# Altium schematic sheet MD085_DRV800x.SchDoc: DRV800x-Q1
size 431 x 279 mm; VersionControl_RevNumber: 1; Date: Not shown in title block; ApprovedBy: Not shown in title block; CheckedBy: Not shown in title block; Author: Not shown in title block; CompanyName: Not shown in title block; DrawnBy: Keerthi Kumanan; Engineer: Not shown in title block; Organization: Not shown in title block; Address1: Not shown in title block; Address2: Not shown in title block; Address3: Not shown in title block; Address4: Not shown in title block; DocumentNumber: 1; Revision: 1; SheetNumber: 4; SheetTotal: 1; PageSetup: Record=PageOptions¦CenterHorizontal=True¦CenterVertical=True¦PrintScale=1.00¦XCorrection=1.00¦YCorrection=1.00¦PrintKind=0¦BorderSize=5000000¦LeftOffset=0¦BottomOffset=0¦Orientation=2¦PaperLength=1000¦PaperWidth=1000¦Scale=100¦PaperSource=15¦PrintQuality=600¦MediaType=1¦DitherType=10¦PaperKind=Letter¦PrintScaleMode=1; VersionControl_ProjFolderRevNumber: 1; VersionControl_RevNumberShort: 1; VersionControl_ProjFolderRevNumberShort: 1
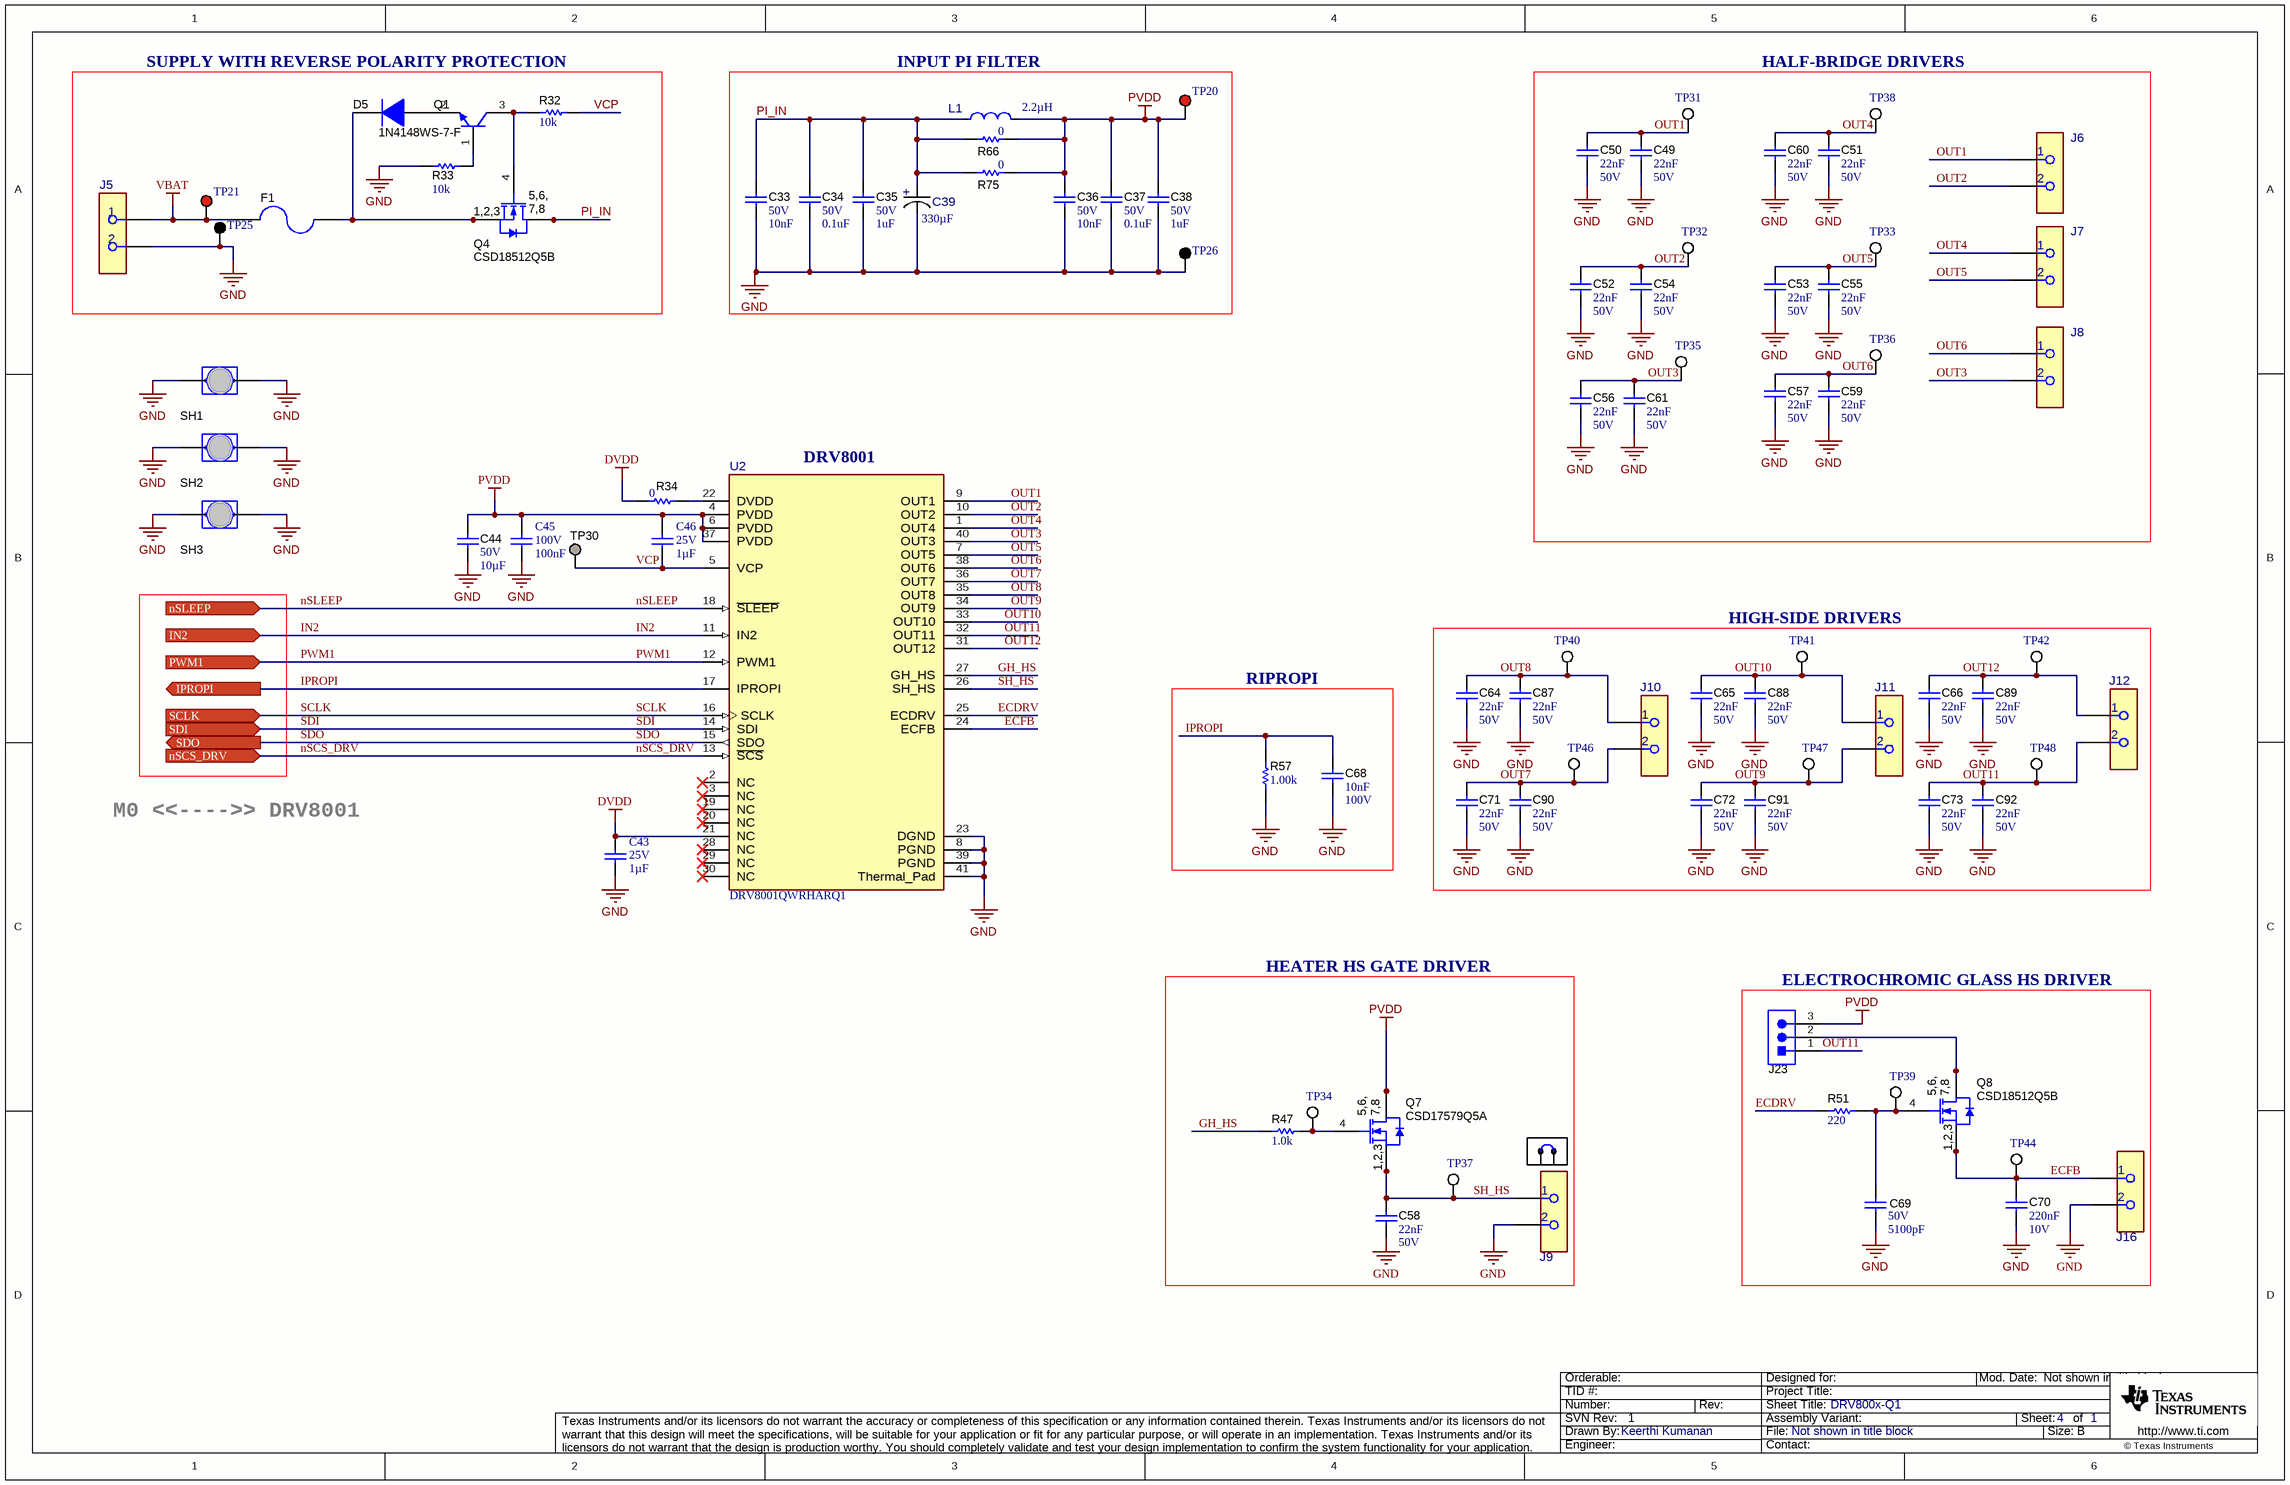
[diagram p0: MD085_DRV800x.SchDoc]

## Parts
C33  VDC_V: 50V  Cap_F: 10nF  [0603L]  (hidden comment: 885012206089)
C34  VDC_V: 50V  ValueDisplayed: 0.1uF  [0603]  (hidden comment: 885012206095)
C35  VDC_V: 50V  ValueDisplayed: 1uF  [0805L]  (hidden comment: 885012207103)
C36  VDC_V: 50V  Cap_F: 10nF  [0603L]  (hidden comment: 885012206089)
C37  VDC_V: 50V  ValueDisplayed: 0.1uF  [0603]  (hidden comment: 885012206095)
C38  VDC_V: 50V  ValueDisplayed: 1uF  [0805L]  (hidden comment: 885012207103)
C39  Cap_F: 330µF  [FP-860020675021_RADIAL-MFG]  (hidden comment: 860020675021)
C43  value 1µF  Rated Voltage (DC): 25V  [WCAP-CSGP_0603_L1.6W0.8H0.8_Reflow]  (hidden comment: 885012206076)
C44  VDC_V: 50V  ValueDisplayed: 10µF  [1206_180]  (hidden comment: 885012108022)
C45  value 100nF  Rated Voltage (DC): 100V  [WCAP-CSGP_0603_L1.6W0.8H0.8_Reflow]  (hidden comment: 885012206120)
C46  value 1µF  Rated Voltage (DC): 25V  [WCAP-CSGP_0603_L1.6W0.8H0.8_Reflow]  (hidden comment: 885012206076)
C49  Cap_F: 22nF  VDC_V: 50V  [0603]  (hidden comment: 885012206091)
C50  Cap_F: 22nF  VDC_V: 50V  [0603]  (hidden comment: 885012206091)
C51  Cap_F: 22nF  VDC_V: 50V  [0603]  (hidden comment: 885012206091)
C52  Cap_F: 22nF  VDC_V: 50V  [0603]  (hidden comment: 885012206091)
C53  Cap_F: 22nF  VDC_V: 50V  [0603]  (hidden comment: 885012206091)
C54  Cap_F: 22nF  VDC_V: 50V  [0603]  (hidden comment: 885012206091)
C55  Cap_F: 22nF  VDC_V: 50V  [0603]  (hidden comment: 885012206091)
C56  Cap_F: 22nF  VDC_V: 50V  [0603]  (hidden comment: 885012206091)
C57  Cap_F: 22nF  VDC_V: 50V  [0603]  (hidden comment: 885012206091)
C58  Cap_F: 22nF  VDC_V: 50V  [0603]  (hidden comment: 885012206091)
C59  Cap_F: 22nF  VDC_V: 50V  [0603]  (hidden comment: 885012206091)
C60  Cap_F: 22nF  VDC_V: 50V  [0603]  (hidden comment: 885012206091)
C61  Cap_F: 22nF  VDC_V: 50V  [0603]  (hidden comment: 885012206091)
C64  Cap_F: 22nF  VDC_V: 50V  [0603]  (hidden comment: 885012206091)
C65  Cap_F: 22nF  VDC_V: 50V  [0603]  (hidden comment: 885012206091)
C66  Cap_F: 22nF  VDC_V: 50V  [0603]  (hidden comment: 885012206091)
C68  Cap_F: 10nF  VDC_V: 100V  [0603]  (hidden comment: 885012206114)
C69  VDC_V: 50V  ValueDisplayed: 5100pF  [0603]  (hidden comment: C0603C512J5GAC7867)
C70  Cap_F: 220nF  VDC_V: 10V  [0603]  (hidden comment: 885012206022)
C71  Cap_F: 22nF  VDC_V: 50V  [0603]  (hidden comment: 885012206091)
C72  Cap_F: 22nF  VDC_V: 50V  [0603]  (hidden comment: 885012206091)
C73  Cap_F: 22nF  VDC_V: 50V  [0603]  (hidden comment: 885012206091)
C87  Cap_F: 22nF  VDC_V: 50V  [0603]  (hidden comment: 885012206091)
C88  Cap_F: 22nF  VDC_V: 50V  [0603]  (hidden comment: 885012206091)
C89  Cap_F: 22nF  VDC_V: 50V  [0603]  (hidden comment: 885012206091)
C90  Cap_F: 22nF  VDC_V: 50V  [0603]  (hidden comment: 885012206091)
C91  Cap_F: 22nF  VDC_V: 50V  [0603]  (hidden comment: 885012206091)
C92  Cap_F: 22nF  VDC_V: 50V  [0603]  (hidden comment: 885012206091)
D5  1N4148WS-7-F  [SOD-323]
F1  0463030.ER  [Fuse_0463]  (value not drawn)
J5  691256610002  [FP-691256610002_HDR2-MFG]  (value not drawn)
J6  691250610002  [FP-691250610002_CONN_TERM_BLOCK2-MFG]  (value not drawn)
J7  691250610002  [FP-691250610002_CONN_TERM_BLOCK2-MFG]  (value not drawn)
J8  691250610002  [FP-691250610002_CONN_TERM_BLOCK2-MFG]  (value not drawn)
J9  691250610002  [FP-691250610002_CONN_TERM_BLOCK2-MFG]  (value not drawn)
J10  691216710002  [FP-691216710002_HDR2-MFG]  (value not drawn)
J11  691216710002  [FP-691216710002_HDR2-MFG]  (value not drawn)
J12  691216710002  [FP-691216710002_HDR2-MFG]  (value not drawn)
J16  691250610002  [FP-691250610002_CONN_TERM_BLOCK2-MFG]  (value not drawn)
J23  TSW-103-07-G-S  [TSW-103-07-G-S]  (value not drawn)
L1  Ind_H: 2.2µH  [FP-74439369022_IND_SMT_11MM6_10MM5-MFG]  (hidden comment: 74439369022)
Q1  BC846BLT1G  [SOT-23L]  (value not drawn)
Q4  CSD18512Q5B  [DNK0008A]
Q7  CSD17579Q5A  [DQJ0008A]
Q8  CSD18512Q5B  [DNK0008A]
R32  ValueDisplayed: 10k  [0603]  (hidden comment: RC0603JR-0710KL)
R33  ValueDisplayed: 10k  [0603]  (hidden comment: RC0603JR-0710KL)
R34  value 0  [0603]  (hidden comment: Resistor)
R47  ValueDisplayed: 1.0k  [0603]  (hidden comment: RC0603JR-071KL)
R51  ValueDisplayed: 220  [0603]  (hidden comment: RC0603FR-07220RL)
R57  ValueDisplayed: 1.00k  [0603]  (hidden comment: RC0603FR-071KL)
R66  ValueDisplayed: 0  [2512_084]  (hidden comment: HCJ2512ZT0R00)
R75  ValueDisplayed: 0  [2512_084]  (hidden comment: HCJ2512ZT0R00)
SH1  Jumper_2p  [Harwin_D3082-05]  (value not drawn)
SH2  Jumper_2p  [Harwin_D3082-05]  (value not drawn)
SH3  Jumper_2p  [Harwin_D3082-05]  (value not drawn)
SH-J21  60900213421  [Wurth_60900213421]  (value not drawn)
TP20  5010  [Keystone5010]  (value not drawn)
TP21  5010  [Keystone5010]  (value not drawn)
TP25  5011  [Keystone5011]  (value not drawn)
TP26  5011  [Keystone5011]  (value not drawn)
TP30  TP_H0.45P0.75  [TP_H045P075]  (value not drawn)  (no BOM)
TP31  5012  [Keystone5012]  (value not drawn)
TP32  5012  [Keystone5012]  (value not drawn)
TP33  5012  [Keystone5012]  (value not drawn)
TP34  5012  [Keystone5012]  (value not drawn)
TP35  5012  [Keystone5012]  (value not drawn)
TP36  5012  [Keystone5012]  (value not drawn)
TP37  5012  [Keystone5012]  (value not drawn)
TP38  5012  [Keystone5012]  (value not drawn)
TP39  5012  [Keystone5012]  (value not drawn)
TP40  5012  [Keystone5012]  (value not drawn)
TP41  5012  [Keystone5012]  (value not drawn)
TP42  5012  [Keystone5012]  (value not drawn)
TP44  5012  [Keystone5012]  (value not drawn)
TP46  5012  [Keystone5012]  (value not drawn)
TP47  5012  [Keystone5012]  (value not drawn)
TP48  5012  [Keystone5012]  (value not drawn)
U2  DRV8001QWRHARQ1  [RHA0040M-MFG]

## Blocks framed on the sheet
SUPPLY WITH REVERSE POLARITY PROTECTION: D5 F1 J5 Q1 Q4 R32 R33 TP21 TP25
INPUT PI FILTER: C33-C39 L1 R66 R75 TP20 TP26
HALF-BRIDGE DRIVERS: C49-C57 C59-C61 J6-J8 TP31-TP33 TP35 TP36 TP38
HIGH-SIDE DRIVERS: C64-C66 C71-C73 C87-C92 J10-J12 TP40-TP42 TP46-TP48
RIPROPI: C68 R57
HEATER HS GATE DRIVER: C58 J9 Q7 R47 SH-J21 TP34 TP37
ELECTROCHROMIC GLASS HS DRIVER: C69 C70 J16 J23 Q8 R51 TP39 TP44

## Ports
IN2 (in), IPROPI (out), nSCS_DRV (in), nSLEEP (in), PWM1 (in), SCLK (in), SDI (in), SDO (out)

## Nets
DVDD: C43.2 R34.2 U2.21(NC)
GND: C33.2 C34.2 C35.2 C36.2 C37.2 C38.2 C39.1(CATHODE) C43.1 C44.2 C45.1 C49.1 C50.1 C51.1 C52.1 C53.1 C54.1 C55.1 C56.1 C57.1 C58.1 C59.1 C60.1 C61.1 C64.1 C65.1 C66.1 C68.2 C69.2 C70.2 C71.1 C72.1 C73.1 C87.1 C88.1 C89.1 C90.1 C91.1 C92.1 J5.2 J9.2 J16.2 R33.1 R57.1 SH1.1 SH1.2 SH2.1 SH2.2 SH3.1 SH3.2 TP25.1 TP26.1 U2.8(PGND) U2.23(DGND) U2.39(PGND) U2.41(Thermal_Pad)
PVDD: C36.1 C37.1 C38.1 C44.1 C45.2 C46.2 J23.3 L1.2 Q7.5(D) Q7.6(D) Q7.7(D) Q7.8(D) Q7.9(D) R66.2 R75.2 TP20.1 U2.4(PVDD) U2.6(PVDD) U2.37(PVDD)
VBAT: F1.2 J5.1 TP21.1
ECDRV: R51.1 U2.25(ECDRV)
ECFB: C70.1 J16.1 Q8.1(S) Q8.2(S) Q8.3(S) TP44.1 U2.24(ECFB)
GH_HS: R47.2 U2.27(GH_HS)
IN2: U2.11(IN2) ; port IN2
IPROPI: C68.1 R57.2 U2.17(IPROPI) ; port IPROPI
nSCS_DRV: U2.13(~{SCS}) ; port nSCS_DRV
nSLEEP: U2.18(~{SLEEP}) ; port nSLEEP
OUT1: C49.2 C50.2 J6.1 TP31.1 U2.9(OUT1)
OUT2: C52.2 C54.2 J6.2 TP32.1 U2.10(OUT2)
OUT3: C56.2 C61.2 J8.2 TP35.1 U2.40(OUT3)
OUT4: C51.2 C60.2 J7.1 TP38.1 U2.1(OUT4)
OUT5: C53.2 C55.2 J7.2 TP33.1 U2.7(OUT5)
OUT6: C57.2 C59.2 J8.1 TP36.1 U2.38(OUT6)
OUT7: C71.2 C90.2 J10.2 TP46.1 U2.36(OUT7)
OUT8: C64.2 C87.2 J10.1 TP40.1 U2.35(OUT8)
OUT9: C72.2 C91.2 J11.2 TP47.1 U2.34(OUT9)
OUT10: C65.2 C88.2 J11.1 TP41.1 U2.33(OUT10)
OUT11: C73.2 C92.2 J12.2 J23.1 TP48.1 U2.32(OUT11)
OUT12: C66.2 C89.2 J12.1 TP42.1 U2.31(OUT12)
PI_IN: C33.1 C34.1 C35.1 C39.2(ANODE) L1.1 Q4.5(D) Q4.6(D) Q4.7(D) Q4.8(D) Q4.9(D) R66.1 R75.1
PWM1: U2.12(PWM1) ; port PWM1
SCLK: U2.16(SCLK) ; port SCLK
SDI: U2.14(SDI) ; port SDI
SDO: U2.15(SDO) ; port SDO
SH_HS: C58.2 J9.1 Q7.1(S) Q7.2(S) Q7.3(S) TP37.1 U2.26(SH_HS)
VCP: C46.1 R32.1 TP30.1 U2.5(VCP)
NetC69_1: C69.1 Q8.4(G) R51.2 TP39.1
NetD5_1: D5.1(K) F1.1 Q4.1(S) Q4.2(S) Q4.3(S)
NetD5_2: D5.2(A) Q1.2(E)
NetJ23_2: J23.2 Q8.5(D) Q8.6(D) Q8.7(D) Q8.8(D) Q8.9(D)
NetQ1_1: Q1.1(B) R33.2
NetQ1_3: Q1.3(C) Q4.4(G) R32.2
NetQ7_4: Q7.4(G) R47.1 TP34.1
NetR34_1: R34.1 U2.22(DVDD)

Not connected (* = marked no-connect by the designer): U2 2(NC)* 3(NC)* 19(NC)* 20(NC)* 28(NC)* 29(NC)* 30(NC)*

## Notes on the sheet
- (near U2) DRV8001
- M0 <<---->> DRV8001

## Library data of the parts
C33 C36 = CMP-0750039-1: CAP, CERM, 0.01 µF, 50 V,+/- 10%, X7R, 0603; Manufacturer: Wurth Elektronik; Polarized: N; AEC Category: Q200; TaMax_C: 125°C; SizeAreaWB_mm2: 4.68; Value: 0.01uF; SizeArea_mm2: 1.28; SizeY_mm: 0.8; SizeZ_mm: 1; ValueDisplayed: 0.01µF; SizeX_mm: 1.6; U/M: EA; Cap_Case: 0603; TaMin_C: -55°C
C34 C37 = CMP-0006837-4: CAP, CERM, 0.1 uF, 50 V, +/- 10%, X7R, 0603; Manufacturer: Wurth Elektronik; TaMin_C: -55°C; Polarized: N; SizeAreaWB_mm2: 4.68; Value1: Unknown; U/M: EA; Value: 0.1uF; TaMax_C: 125°C; SizeZ_mm: 1; SizeX_mm: 1.6; SizeY_mm: 0.8; SizeArea_mm2: 1.28; Cap_F: 100nF; AEC Category: Q200
C35 C38 = CMP-0007696-2: CAP, CERM, 1 uF, 50 V, +/- 10%, X7R, 0805; Manufacturer: Wurth Elektronik; TaMin_C: -55°C; Polarized: N; SizeAreaWB_mm2: 6.75; Value1: Unknown; U/M: EA; Value: 1uF; TaMax_C: 125°C; SizeZ_mm: 1.45; SizeX_mm: 2; SizeY_mm: 1.25; Cap_Case: 0805; SizeArea_mm2: 2.5; Cap_F: 1µF; AEC Category: Q200
C39 = CMP-0087013-2: Electrolytic Capacitor, 330 uF, 50 V, WCAP-ATG5 Series, 20%, Radial Leaded, 10 mm; Manufacturer: Wurth Electronics; SizeZ_mm: 17.5mm; AEC Qualified: No; IRMS_A: 450mA; ValueDisplayed: 330uF
C43 C46 = CMP-0108290-1: WCAP-CSGP Multilayer Ceramic Chip Capacitor, General Purpose, size 0603, X7R, 1µF, 25VDC; Manufacturer: Wurth Elektronik; Capacitance Tolerance: +/-10%; Case/Size Code: 0603; Dissipation Factor: 10%; Insulation Resistance: 0.5GOhm; Technical Reference: X7R0603105K025DFCT10000
C44 = CMP-0081454-1: CAP, CERM, 10 µF, 50 V,+/- 20%, X5R, 1206; Manufacturer: Wurth Elektronik; TaMin_C: -55°C; Polarized: N; SizeAreaWB_mm2: 10.92; U/M: EA; Value: 10uF; TaMax_C: 125°C; SizeZ_mm: 1.8; SizeX_mm: 3.2; SizeY_mm: 1.6; Cap_Case: 1206; SizeArea_mm2: 5.12; AEC Category: Q200
C45 = CMP-0108322-1: WCAP-CSGP Multilayer Ceramic Chip Capacitor, General Purpose, size 0603, X7R, 100nF, 100VDC; Manufacturer: Wurth Elektronik; Capacitance Tolerance: +/-10%; Case/Size Code: 0603; Dissipation Factor: 5%; Insulation Resistance: 1GOhm; Technical Reference: X7R0603104K100DFCT10000
C49-C61 C64-C66 C71-C73 C87-C92 = CMP-0006836-4: CAP, CERM, 0.022 uF, 50 V, +/- 10%, X7R, 0603; Manufacturer: Wurth Elektronik; TaMin_C: -55°C; Polarized: N; SizeAreaWB_mm2: 4.68; Value1: Unknown; U/M: EA; TaMax_C: 125°C; SizeZ_mm: 1; SizeX_mm: 1.6; SizeY_mm: 0.8; SizeArea_mm2: 1.28; AEC Category: Q200
C68 = CMP-0079993-1: CAP, CERM, 0.01 µF, 100 V,+/- 10%, X7R, 0603; Manufacturer: Wurth Elektronik; TaMin_C: -55°C; Polarized: N; SizeAreaWB_mm2: 4.68; U/M: EA; Value: 0.01uF; TaMax_C: 105°C; SizeZ_mm: 1; SizeX_mm: 1.6; SizeY_mm: 0.8; SizeArea_mm2: 1.28; AEC Category: Q200; ValueDisplayed: 0.01µF
C69 = CMP-0080094-1: CAP, CERM, 5100 pF, 50 V,+/- 5%, C0G/NP0, 0603; Manufacturer: Kemet; Cap_F: 5.1nF; SizeAreaWB_mm2: 4.68; SizeArea_mm2: 1.28; AEC Qualified: N; AEC Category: Q200; Value: 5100pF; TaMax_C: 125°C; SizeZ_mm: 1; Green_REACh: Passed; TaMin_C: -55°C; SizeY_mm: 0.8; Green_Lifecycle: Active; U/M: EA; SizeX_mm: 1.6
C70 = CMP-0074687-3: CAP, CERM, 0.22 µF, 10 V,+/- 10%, X7R, 0603; Manufacturer: Wurth Elektronik; TaMin_C: -55°C; Polarized: N; SizeAreaWB_mm2: 4.68; U/M: EA; Value: 0.22uF; TaMax_C: 125°C; SizeZ_mm: 1.0; SizeX_mm: 1.6; SizeY_mm: 0.8; SizeArea_mm2: 1.28; AEC Category: Q200; ValueDisplayed: 0.22µF
D5 = CMP-0079597-2: Diode, Switching, 75 V, 0.15 A, AEC-Q101, SOD-323; Manufacturer: Diodes Inc.; Value: 75V; Vf_V: 1.25V; Value1: 0.15A; Io_A: 150mA; TJmax_C: 150°C; AEC Category: Q101; AEC Qualified: Y; SizeArea_mm2: 3.645; SizeAreaWB_mm2: 8.695; SizeX_mm: 2.7; SizeY_mm: 1.35; SizeZ_mm: 1
F1 = CMP-0077200-3: Fuse, 30 A, 250 VAC, 100 VDC, SMD; Manufacturer: Littelfuse; VAC_V: 250V; SizeAreaWB_mm2: 61.952; Rtyp_Ohm: 1.93m; SizeArea_mm2: 31.512; MeltingTyp: 916; Irating_A: 30A; SizeZ_mm: 3.12; VDC_V: 100V; SizeX_mm: 10.1; Interrupt_AC: 100A; Interrupt_DC: 50A; Fuse Speed: Fast; Fuse Technology: Board Mount; TaMax_C: 125°C; TaMin_C: -55°C
J5 = CMP-0086764-1: 2 Position Wire to Board Terminal Block Horizontal with Board 0.400" (10.16mm) Through Hole; Manufacturer: Wurth; Current_A: 57A; Voltage_V: 750V; ContactFinish: Zinc; Row_Count: 1
J6-J9 J16 = CMP-0093233-2: 2 Position Wire to Board Terminal Block Horizontal with Board 0.250" (6.35mm) Through Hole; Manufacturer: Wurth Electronics; Current_A: 32A; Conn Gender: Female; Row_Count: 1; ContactFinish: Zinc; SizeZ_mm: 21.6mm; Max Wire Gauge: 10; Min Wire Gauge: 30; Voltage_V: 450V; AEC Qualified: No; Is Female: yes
J10-J12 = CMP-0096350-1: 2 Position Wire to Board Terminal Block Horizontal with Board 0.197" (5.00mm) Through Hole; Manufacturer: Wurth Electronics; Row_Count: 1; AEC Qualified: No; DUT-Pitch_mm: 5mm; Max Wire Gauge: 12; Is Female: yes; ContactFinish: Tin,Nickel; Min Wire Gauge: 30; Current_A: 14A; Voltage_V: 300V; SizeZ_mm: 13.9mm; Conn Gender: Female
J23 = CMP-0075407-2: Header, 100mil, 3x1, Gold, TH; Manufacturer: Samtec; Pitch_mm: 2.54; Gender: Male; Cert_CSA: Y; Row_Count: 1; Cert_CULUS: N; Current_A: 6.3A; Green_Lifecycle: Active; Green_REACh: Passed; Voltage_V: 550V
L1 = CMP-0087162-1: FIXED IND 2.2UH 16A 2.2 MOHM; Manufacturer: Wurth Electronics; Material: Composite; Isat: 34A; DCR_ohm: 2.42m; SizeZ_mm: 9.1mm; AEC Qualified: No; Symbol Name: SYM-74439369022
Q1 = CMP-0000375-2: Transistor, NPN, 65 V, 0.1 A, SOT-23; Manufacturer: ON Semiconductor; CompType: BJT; PNP: 0; NPN: 1; Vceo_V: 65V; Vcesat1_V: 700mV; Value: 65 V; IcRated_A: 100mA; Value1: 0.1 A; HfeMax: 450; TaMin_C: -55°C; TaMax_C: 150°C; U/M: EA; AEC Category: Q101; SizeArea_mm2: 7.5; SizeAreaWB_mm2: 14; SizeX_mm: 2.5; SizeY_mm: 3; SizeZ_mm: 1.1
Q4 Q8 = CMP-0000713-2: MOSFET, N-CH, 40 V, 100 A, DNK0008A (VSON-CLIP-8); Alternate Manufacturer: None; Manufacturer: Texas Instruments; SizeZ_mm: 1; ChType: N; Value2: 37 nC; Value1: 0.002; VdsMax_V: 40V; SizeX_mm: 6; SizeY_mm: 5; Vgs_V: 20V; Value: 40V; Rdson45_ohm: 2.3m; SizeArea_mm2: 30; AEC Category: Q101; IdsMax_A: 100A; SizeAreaWB_mm2: 56; U/M: EA; QgTyp_nC: 37
Q7 = CMP-0000594-1: MOSFET, N-CH, 30 V, 25 A, DQJ0008A (VSONP-8); Alternate Manufacturer: None; Manufacturer: Texas Instruments; SizeZ_mm: 1.1; ChType: N; Value2: 11.6 nC; Value1: 0.013; VdsMax_V: 30V; SizeX_mm: 6; SizeAreaWB_mm2: 55.2; SizeY_mm: 4.9; Vgs_V: 20V; QgTyp_nC: 11.6; Value: 30V; Rdson45_ohm: 13.3m; SizeArea_mm2: 29.4; AEC Category: Q101; IdsMax_A: 25A; U/M: EA
R32 R33 = CMP-0025886-5: RES, 10 k, 5%, 0.1 W, 0603; Manufacturer: Yageo; Value: 10k; SizeY_mm: 0.8; SizeArea_mm2: 1.28; EIA_Code: E24; Power_W: 100mW; SizeX_mm: 1.6; Value2: 0.1W; Value_Code: 10k0; VDC_V: 75V; SizeZ_mm: 1; AEC Qualified: N; AEC Category: Q200; TempCo: 100 ppm/C; SizeAreaWB_mm2: 4.68
R34 = CMP-0025885-5: RES, 0, 5%, 0.1 W, 0603; PartNumber: RC0603JR-070RL; Manufacturer: Yageo; Power_W: 100mW; VDC_V: 75V; AEC Qualified: N; SizeZ_mm: 1; AEC Category: Q200; EIA_Code: E24; SizeArea_mm2: 1.28; SizeAreaWB_mm2: 4.68; SizeX_mm: 1.6; SizeY_mm: 0.8; TempCo: 200 ppm/C; Value2: 0.1W; Value_Code: 0000
R47 = CMP-0025899-5: RES, 1.0 k, 5%, 0.1 W, 0603; Manufacturer: Yageo; Power_W: 100mW; TempCo: 100 ppm/C; Value_Code: 1k00; Value: 1.0k; EIA_Code: E24; Res_ohm: 1k; SizeX_mm: 1.6; SizeY_mm: 0.8; SizeZ_mm: 1; Value2: 0.1W; SizeArea_mm2: 1.28; AEC Qualified: N; VDC_V: 75V; AEC Category: Q200; SizeAreaWB_mm2: 4.68
R51 = CMP-0022918-5: RES, 220, 1%, 0.1 W, 0603; Manufacturer: Yageo; Power_W: 100mW; TempCo: 100 ppm/C; Value_Code: 220R; Value: 220; SizeX_mm: 1.6; SizeY_mm: 0.8; SizeZ_mm: 1; Value2: 0.1W; SizeArea_mm2: 1.28; AEC Qualified: N; VDC_V: 75V; AEC Category: Q200; SizeAreaWB_mm2: 4.68
R57 = CMP-0022895-5: RES, 1.00 k, 1%, 0.1 W, 0603; Manufacturer: Yageo; Power_W: 100mW; TempCo: 100 ppm/C; Value_Code: 1k00; Value: 1.00k; EIA_Code: E96; Res_ohm: 1k; SizeX_mm: 1.6; SizeY_mm: 0.8; SizeZ_mm: 1; Value2: 0.1W; SizeArea_mm2: 1.28; AEC Qualified: N; VDC_V: 75V; AEC Category: Q200; SizeAreaWB_mm2: 4.68
R66 R75 = CMP-0078790-1: RES, 0, 0.05%, 2 W, AEC-Q200 Grade 0, 2512; Manufacturer: Stackpole Electronics Inc; AEC Qualified: Y; AEC Category: Q200; Value: 0; Power_W: 2W
SH1-SH3 = CMP-0075110-1: 1mm Uninsulated Shorting Plug, 10.16mm spacing, TH; PartNumber: D3082-05; Manufacturer: Harwin; CNHeader: False; CompType: Jumper Wire; Green_Lifecycle: Active; Green_REACh: Passed
SH-J21 = CMP-0003761-2: Shunt, 2.54mm, Gold, Black; Manufacturer: Wurth Elektronik
TP20 TP21 = CMP-0055147-2: Test Point, Multipurpose, Red, TH; Manufacturer: Keystone Electronics; CNHeader: FALSE; Green_Lifecycle: Active; Green_REACh: Passed; ContactFinish: Silver; CT: TRUE
TP25 TP26 = CMP-0055148-2: Test Point, Multipurpose, Black, TH; Manufacturer: Keystone Electronics; CNHeader: FALSE; Green_Lifecycle: Active; Green_REACh: Passed; ContactFinish: Silver; CT: TRUE
TP30 = CMP-0003719-1: Testpoint; Manufacturer: Texas Instruments; CompType: Pad
TP31-TP42 TP44 TP46-TP48 = CMP-0055149-2: Test Point, Multipurpose, White, TH; Manufacturer: Keystone Electronics; ContactFinish: Silver; CT: TRUE; CNHeader: FALSE; Green_Lifecycle: Active; Green_REACh: Passed
U2 = CMP-0121851-2: Automotive Multi-function Driver with Integrated Half-bridges &HighSide and Current Sensing & Advanced Diagnostics; Manufacturer: Texas Instruments; SizeZ_mm: 1mm; AEC Qualified: Yes; AEC Grade: Grade 1; Max Supply Voltage: 35V; Min Supply Voltage: 4.5V; Number Of Outputs: 12; Standoff Height: 0mm; TaMax_C: +125°C; TaMin_C: -40°C; TJmax_C: +150°C; AEC Category: Q200; CompType: IC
